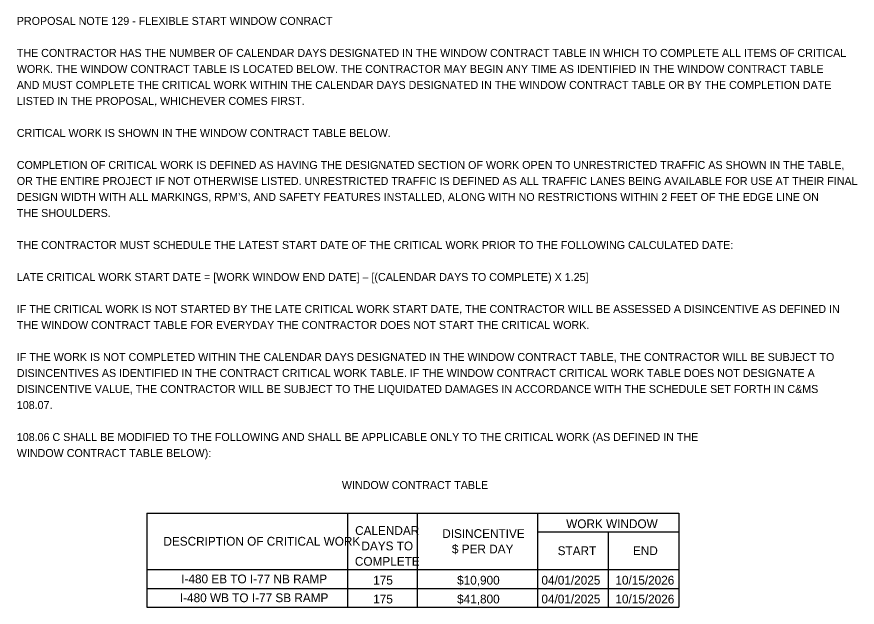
# Model space of a CAD drawing. Extents: x 0 to 52.3, y 0 to 22.
# Drawn here: x 37.63 to 52.33, y 10.81 to 21.14 of the extents above; entities that cross this region are included whole.
import ezdxf

# ---------------------------------------------------------------- set-up
doc = ezdxf.new("R2010")
doc.units = 0
doc.layers.add('SH_Text', color=7, linetype='Continuous')

msp = doc.modelspace()

# ---------------------------------------------------------------- linework, layer by layer
at = {"layer": 'SH_Text'}
for p, q in [((39.904, 12.46), (49.21, 12.46)), ((39.904, 12.46), (39.904, 10.813)), ((43.412, 12.46), (43.412, 10.813)), ((44.631, 12.46), (44.631, 10.813)), ((46.739, 12.46), (46.739, 10.813)), ((49.21, 12.46), (49.21, 10.813)), ((46.739, 12.131), (49.21, 12.131)), ((47.974, 12.131), (47.974, 10.813)), ((39.904, 11.472), (49.21, 11.472)), ((39.904, 11.142), (49.21, 11.142)), ((39.904, 10.813), (49.21, 10.813))]:
    msp.add_line(p, q, dxfattribs=at)

# ---------------------------------------------------------------- texts
for s, height, p in [('PROPOSAL NOTE 129 - FLEXIBLE START WINDOW CONRACT', 0.14, (37.627, 21)), ('THE CONTRACTOR HAS THE NUMBER OF CALENDAR DAYS DESIGNATED IN THE WINDOW CONTRACT TABLE IN WHICH TO COMPLETE ALL ITEMS OF CRITICAL ', 0.14, (37.627, 20.44)), ('WORK. THE WINDOW CONTRACT TABLE IS LOCATED BELOW. THE CONTRACTOR MAY BEGIN ANY TIME AS IDENTIFIED IN THE WINDOW CONTRACT TABLE ', 0.14, (37.627, 20.16)), ('AND MUST COMPLETE THE CRITICAL WORK WITHIN THE CALENDAR DAYS DESIGNATED IN THE WINDOW CONTRACT TABLE OR BY THE COMPLETION DATE ', 0.14, (37.627, 19.88)), ('LISTED IN THE PROPOSAL, WHICHEVER COMES FIRST.', 0.14, (37.627, 19.6)), ('CRITICAL WORK IS SHOWN IN THE WINDOW CONTRACT TABLE BELOW.', 0.14, (37.627, 19.04)), ('COMPLETION OF CRITICAL WORK IS DEFINED AS HAVING THE DESIGNATED SECTION OF WORK OPEN TO UNRESTRICTED TRAFFIC AS SHOWN IN THE TABLE, ', 0.14, (37.627, 18.48)), ('OR THE ENTIRE PROJECT IF NOT OTHERWISE LISTED. UNRESTRICTED TRAFFIC IS DEFINED AS ALL TRAFFIC LANES BEING AVAILABLE FOR USE AT THEIR FINAL ', 0.14, (37.627, 18.2)), ('DESIGN WIDTH WITH ALL MARKINGS, RPM’S, AND SAFETY FEATURES INSTALLED, ALONG WITH NO RESTRICTIONS WITHIN 2 FEET OF THE EDGE LINE ON ', 0.14, (37.627, 17.92)), ('THE SHOULDERS.', 0.14, (37.627, 17.64)), ('THE CONTRACTOR MUST SCHEDULE THE LATEST START DATE OF THE CRITICAL WORK PRIOR TO THE FOLLOWING CALCULATED DATE:', 0.14, (37.627, 17.08)), ('LATE CRITICAL WORK START DATE = [WORK WINDOW END DATE] – [(CALENDAR DAYS TO COMPLETE) X 1.25] ', 0.14, (37.627, 16.52)), ('IF THE CRITICAL WORK IS NOT STARTED BY THE LATE CRITICAL WORK START DATE, THE CONTRACTOR WILL BE ASSESSED A DISINCENTIVE AS DEFINED IN ', 0.14, (37.627, 15.96)), ('THE WINDOW CONTRACT TABLE FOR EVERYDAY THE CONTRACTOR DOES NOT START THE CRITICAL WORK.', 0.14, (37.627, 15.68)), ('IF THE WORK IS NOT COMPLETED WITHIN THE CALENDAR DAYS DESIGNATED IN THE WINDOW CONTRACT TABLE, THE CONTRACTOR WILL BE SUBJECT TO ', 0.14, (37.627, 15.12)), ('DISINCENTIVES AS IDENTIFIED IN THE CONTRACT CRITICAL WORK TABLE. IF THE WINDOW CONTRACT CRITICAL WORK TABLE DOES NOT DESIGNATE A ', 0.14, (37.627, 14.84)), ('DISINCENTIVE VALUE, THE CONTRACTOR WILL BE SUBJECT TO THE LIQUIDATED DAMAGES IN ACCORDANCE WITH THE SCHEDULE SET FORTH IN C&MS ', 0.14, (37.627, 14.56)), ('108.07.', 0.14, (37.627, 14.28)), ('108.06 C SHALL BE MODIFIED TO THE FOLLOWING AND SHALL BE APPLICABLE ONLY TO THE CRITICAL WORK (AS DEFINED IN THE', 0.14, (37.627, 13.72)), ('WINDOW CONTRACT TABLE BELOW):', 0.14, (37.627, 13.44)), ('WINDOW CONTRACT TABLE', 0.14, (43.314, 12.88)), ('WORK WINDOW', 0.154, (47.238, 12.196)), ('CALENDAR', 0.154, (43.546, 12.077)), ('DISINCENTIVE', 0.154, (45.07, 12.024)), ('DESCRIPTION OF CRITICAL WORK', 0.154, (40.192, 11.889)), ('DAYS TO', 0.154, (43.656, 11.807)), ('$ PER DAY', 0.154, (45.239, 11.754)), ('START', 0.154, (47.089, 11.724)), ('END', 0.154, (48.406, 11.724)), ('COMPLETE', 0.154, (43.542, 11.538)), ('I-480 EB TO I-77 NB RAMP', 0.154, (40.504, 11.23)), ('175', 0.154, (43.862, 11.208)), ('$10,900', 0.154, (45.33, 11.208)), ('04/01/2025', 0.154, (46.805, 11.208)), ('10/15/2026', 0.154, (48.099, 11.208)), ('I-480 WB TO I-77 SB RAMP', 0.154, (40.48, 10.901)), ('175', 0.154, (43.862, 10.879)), ('$41,800', 0.154, (45.33, 10.879)), ('04/01/2025', 0.154, (46.805, 10.879)), ('10/15/2026', 0.154, (48.099, 10.879))]:
    msp.add_text(s, height=height, dxfattribs=at).set_placement(p)

doc.saveas('drawing.dxf')
